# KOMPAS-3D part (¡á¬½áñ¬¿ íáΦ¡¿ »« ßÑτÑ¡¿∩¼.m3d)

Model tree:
1. Эскиз:1
2. Смещенная плоскость:28
     Расстояние = 5.4
3. Смещенная плоскость:29
     Расстояние = 5.4
4. Смещенная плоскость:30
     Расстояние = 5.4
5. Смещенная плоскость:31
     Расстояние = 5.4
6. Смещенная плоскость:32
     Расстояние = 5.4
7. Смещенная плоскость:33
     Расстояние = 5.4
8. Смещенная плоскость:34
     Расстояние = 5.4
9. Эскиз:10
10. Эскиз:11
11. Эскиз:12
12. Эскиз:13
13. Эскиз:14
14. Эскиз:15
15. Эскиз:16
16. Поверхность по сечениям:12
     Толщина стенки 1 = 1; Толщина стенки 2 = 1
17. Заплатка:3
18. Сшивка поверхностей:6
     Точность сшивки = 0.01
19. Придать толщину:8
     Толщина стенки 1 = 2; Толщина стенки 2 = 1
20. Эскиз:49
21. Вырезать элемент выдавливания:15
     Расстояние 2 = 39.8; Расстояние 1 = 0.755166
22. Эскиз:50
23. Вырезать элемент выдавливания:16
     Расстояние 2 = 39.8; Расстояние 1 = 0.391561
24. Эскиз:51
25. Вырезать элемент выдавливания:17
     Расстояние 2 = 39.8; Расстояние 1 = 0.391561
26. Эскиз:52
27. Вырезать элемент выдавливания:18
     Расстояние 2 = 39.8; Расстояние 1 = 10
28. Эскиз:53
29. Вырезать элемент выдавливания:19
     Расстояние 2 = 39.8; Расстояние 1 = 10
30. Эскиз:54
31. Вырезать элемент выдавливания:20
     Расстояние 2 = 85.0258; Расстояние 1 = 103.202
32. Скругление:1
     Радиус = 0.5
33. Скругление:2
     Радиус = 0.5
34. Скругление:3
     Радиус = 0.5
35. Скругление:4
     Радиус = 0.5
36. Скругление:5
     Радиус = 0.5
37. Скругление:6
     Радиус = 0.5
38. Скругление:7
     Радиус = 0.5
39. Скругление:8
     Радиус = 0.5

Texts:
  накладки башни по сечениям
  Сплав АЛ8  ГОСТ 1583-93
  stalker61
